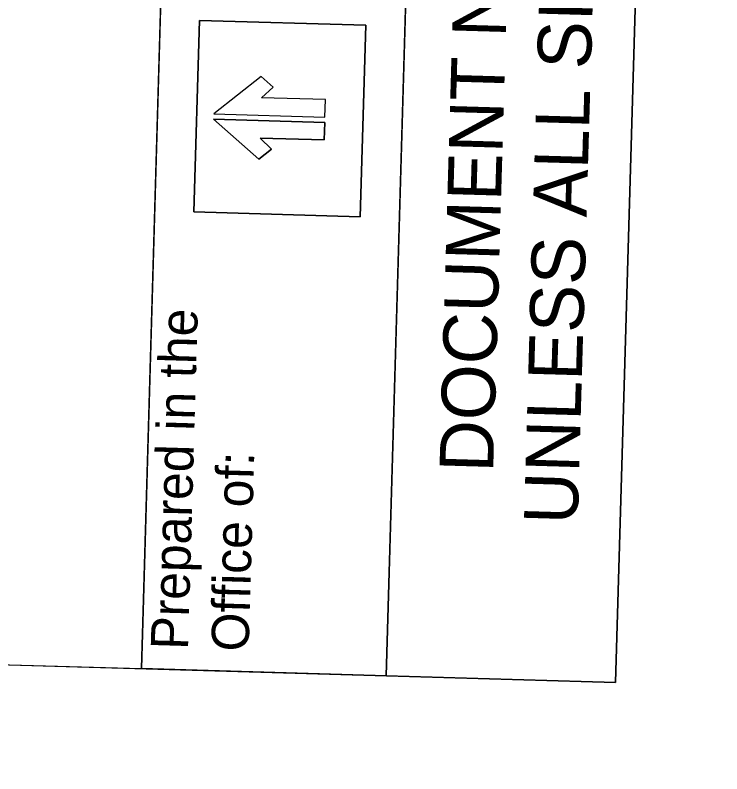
# Model space of a CAD drawing. Extents: x 2097002 to 2098146, y 685127 to 687089.
# Drawn here: x 2097242.5 to 2097318.3, y 686598.1 to 686679.4 of the extents above; entities that cross this region are included whole.
import ezdxf

# ---------------------------------------------------------------- set-up
doc = ezdxf.new("R2010")
doc.units = 0
for name, color, linetype in [('Sheet Block Title CELL', 7, 'Continuous'), ('Sheet Layout Plan Border', 7, 'Continuous'), ('Sheet Sticker Exception Certification CELL', 7, 'Continuous'), ('Sheet Title CELL', 7, 'Continuous')]:
    doc.layers.add(name, color=color, linetype=linetype)

msp = doc.modelspace()

# ---------------------------------------------------------------- linework, layer by layer
at = {"layer": 'Sheet Block Title CELL'}
for points in [[(2097256.008, 686609.368), (2097261.821, 686809.341), (2097288.066, 686808.578), (2097282.253, 686608.605)], [(2097261.64, 686658.328), (2097262.237, 686678.876), (2097280.072, 686678.358), (2097279.475, 686657.809)], [(2097263.771, 686668.849), (2097275.697, 686668.502), (2097275.751, 686670.381), (2097268.873, 686670.581), (2097270.138, 686671.709), (2097268.863, 686672.841)]]:
    msp.add_lwpolyline(points, close=True, dxfattribs=at)
for points in [[(2097262.237, 686678.876), (2097261.64, 686658.328), (2097279.475, 686657.809), (2097280.072, 686678.358), (2097262.237, 686678.876)], [(2097263.771, 686668.849), (2097275.697, 686668.502), (2097275.751, 686670.381), (2097268.873, 686670.581), (2097270.138, 686671.709), (2097268.863, 686672.841), (2097263.771, 686668.849)], [(2097263.755, 686668.271), (2097275.68, 686667.924), (2097275.625, 686666.046), (2097268.747, 686666.246), (2097269.944, 686665.046), (2097268.606, 686663.991), (2097263.755, 686668.271)], [(2097268.606, 686663.991), (2097269.944, 686665.046), (2097268.747, 686666.246), (2097275.625, 686666.046), (2097275.68, 686667.924), (2097263.755, 686668.271), (2097268.606, 686663.991)]]:
    msp.add_lwpolyline(points, dxfattribs=at)
at = {"layer": 'Sheet Layout Plan Border'}
msp.add_lwpolyline([(2098110.676, 686386.516), (2098090.846, 685704.417), (2097236.932, 685318.955), (2097029.373, 685324.989), (2097061.334, 686424.416), (2097062.771, 686473.85), (2097066.87, 686614.866), (2097306.863, 686607.889), (2097310.433, 686730.691), (2098032.534, 686709.699), (2098023.213, 686389.059)], close=True, dxfattribs=at)
at = {"layer": 'Sheet Sticker Exception Certification CELL'}
for p, q in [((2097282.253, 686608.605), (2097288.343, 686818.094)), ((2097312.953, 686817.379), (2097306.863, 686607.889)), ((2097306.863, 686607.889), (2097282.253, 686608.605))]:
    msp.add_line(p, q, dxfattribs=at)
at = {"layer": 'Sheet Title CELL'}
for p in [(2097262.098, 686818.857), (2097066.87, 686614.866)]:
    msp.add_line(p, (2097256.008, 686609.368), dxfattribs=at)

# ---------------------------------------------------------------- texts
at = {"layer": 'Sheet Block Title CELL'}
for s, height, p in [('Prepared in the ', 4.00116, (2097261.001, 686611.346)), ('Office of:', 4.0012, (2097267.5, 686611.157))]:
    msp.add_text(s, height=height, rotation=88.33483, dxfattribs=at).set_placement(p)
at = {"layer": 'Sheet Sticker Exception Certification CELL'}
for s, p in [('UNLESS ALL SIGNATURES COMPLETED', (2097302.79, 686624.777)), ('DOCUMENT NOT CONSIDERED FINAL', (2097293.729, 686630.356))]:
    msp.add_text(s, height=5.76232, rotation=88.33483, dxfattribs=at).set_placement(p)

doc.saveas('drawing.dxf')
